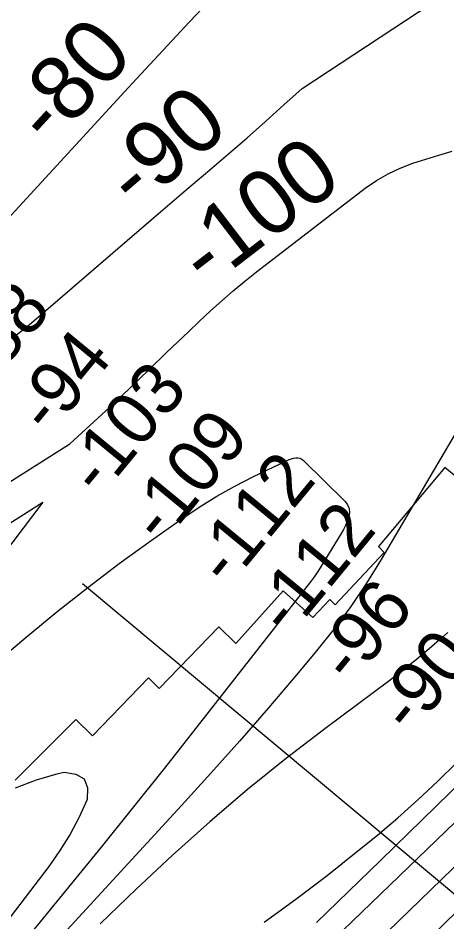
# Model space of a CAD drawing. Extents: x 3598634 to 3636690, y 517270 to 542944.
# Drawn here: x 3604825 to 3605373, y 526222 to 527377 of the extents above; entities that cross this region are included whole.
import ezdxf

# ---------------------------------------------------------------- set-up
doc = ezdxf.new("R2010")
doc.units = 0
for name, color, linetype in [('V-CHAN-NAID', 7, 'Continuous'), ('V-RIVR-RANG', 7, 'Continuous'), ('V-RRAP-RVMT', 7, 'Continuous'), ('V-STRM-FLOW', 7, 'Continuous'), ('V-TOPO-DPTH', 7, 'Continuous'), ('V-TOPO-MAJR', 7, 'Continuous'), ('V-TOPO-MAJR-IDEN', 7, 'Continuous'), ('V-TOPO-MINR', 7, 'Continuous'), ('V-TOPO-MINR-IDEN', 7, 'Continuous')]:
    doc.layers.add(name, color=color, linetype=linetype)

msp = doc.modelspace()

# ---------------------------------------------------------------- linework, layer by layer
at = {"layer": 'V-RIVR-RANG'}
msp.add_line((3605752.3, 525947.2), (3604907, 526654.1), dxfattribs=at)
at = {"layer": 'V-RRAP-RVMT'}
for p, q in [((3605370, 526802.8), (3605285.1, 526701.7)), ((3605523.7, 526673.8), (3605370, 526802.8)), ((3605292.5, 526694), (3605229.9, 526626.9)), ((3605285.1, 526701.7), (3605292.5, 526694)), ((3605163.3, 526645), (3605102.8, 526577.8)), ((3605201.4, 526610.7), (3605163.3, 526645)), ((3605223.1, 526633.9), (3605201.4, 526610.7)), ((3605229.9, 526626.9), (3605223.1, 526633.9)), ((3605081, 526598.9), (3605005, 526520.2)), ((3605102.8, 526577.8), (3605081, 526598.9)), ((3604991.2, 526533.6), (3604919.5, 526459.4)), ((3605005, 526520.2), (3604991.2, 526533.6)), ((3604898.3, 526480.6), (3604820.7, 526403)), ((3604919.5, 526459.4), (3604898.3, 526480.6))]:
    msp.add_line(p, q, dxfattribs=at)
at = {"layer": 'V-STRM-FLOW'}
msp.add_lwpolyline([(3604713.3, 526667.7), (3604856.2, 526758.4), (3604753.9, 526623.5)], dxfattribs=at)
at = {"layer": 'V-TOPO-DPTH'}
msp.add_lwpolyline([(3605155.1, 526007.8), (3605497.3, 526345.9)], dxfattribs=at)
msp.add_lwpolyline([(3605155.1, 526007.8), (3605497.3, 526345.9)], dxfattribs=at)
at = {"layer": 'V-TOPO-MAJR'}
for points in [[(3604098.7, 526331.4), (3604890.7, 526832.8), (3604916.3, 526856.3), (3604941.7, 526879.9), (3604967, 526903.8), (3604992, 526927.9), (3605014.4, 526949.6), (3605028.3, 526963), (3605042.3, 526976.3), (3605056.4, 526989.6), (3605070.5, 527002.9), (3605084.8, 527015.8), (3605099.4, 527028.5), (3605114.3, 527040.8), (3605129.4, 527052.8), (3605268.3, 527159.7), (3605282.5, 527169.5), (3605297.3, 527178.3), (3605312.9, 527185.5), (3605329.1, 527191.6), (3605345.7, 527196.9), (3605362.4, 527202), (3605379.1, 527206.9)], [(3605519.2, 527085.7), (3605500.7, 527048.2), (3605480.6, 527011.4), (3605288.6, 526685.1), (3605269.7, 526654.7), (3605249.8, 526625), (3605228.4, 526596.3), (3605206.1, 526568.3), (3605180.6, 526537.9), (3605144.5, 526495.5), (3605108, 526453.4), (3605071, 526411.8), (3605033.5, 526370.6), (3604541.9, 525836.1), (3604531.7, 525824.9), (3604521.6, 525813.6), (3604511.7, 525802.2), (3604501.9, 525790.7), (3604418.3, 525691.8), (3604367.5, 525630.2), (3604317.7, 525567.9), (3604269.3, 525504.4)], [(3604758.4, 525688), (3605476.3, 526383.5)]]:
    msp.add_lwpolyline(points, dxfattribs=at)
at = {"layer": 'V-TOPO-MINR'}
for points in [[(3606331.2, 528483.3), (3606171, 528346.6), (3606089, 528276.3), (3606007.2, 528205.6), (3605925.9, 528134.5), (3605192.6, 527528.5), (3605117.8, 527450.9), (3605043.8, 527372.4), (3604970.3, 527293.5), (3604747.9, 527052.1)], [(3604818.6, 526969.3), (3604826.3, 526975.3), (3604833.9, 526981.4), (3604841.5, 526987.7), (3604997.7, 527121.7), (3605021.6, 527142.2), (3605045.5, 527162.7), (3605069.5, 527183.2), (3605093.4, 527203.7), (3605117.2, 527224.3), (3605140.8, 527245.1), (3605164.3, 527266.2), (3605187.5, 527287.4), (3605715.9, 527635.2)], [(3604710.8, 526480.7), (3604835, 526585.8), (3604874, 526618), (3604913.5, 526649.4), (3604953.8, 526679.8), (3604994.7, 526709.5), (3605033.6, 526737), (3605055.8, 526751.8), (3605078.4, 526765.9), (3605101.7, 526778.9), (3605125.5, 526791.1), (3605168.4, 526811.8), (3605171.1, 526813), (3605173.8, 526813.9), (3605176.6, 526814.6), (3605179.4, 526815), (3605182.1, 526815), (3605184.7, 526814.5), (3605187.1, 526813.3), (3605189.3, 526811.7), (3605242.5, 526759.4), (3605245.7, 526755), (3605247.7, 526750.2)], [(3605247.7, 526750.2), (3605248.1, 526745.1), (3605247.3, 526739.7), (3605245.3, 526734.1), (3605243, 526728.7), (3605240.3, 526723.4), (3605237.4, 526718.2), (3605208.3, 526670.9), (3605205.9, 526667.2), (3605203.5, 526663.5), (3605200.9, 526660), (3605198.2, 526656.5), (3605011.6, 526418.4), (3604930.9, 526317.2), (3604849, 526216.9), (3604765.5, 526118.1), (3604680.9, 526020.1), (3604540.8, 525860.6), (3604525.5, 525843), (3604510.3, 525825.4), (3604495.2, 525807.6), (3604480.2, 525789.8), (3604361.5, 525647.7), (3604287.8, 525558.3)], [(3605373.6, 526591.7), (3605366.6, 526585.4), (3605350, 526570.9), (3605333.1, 526556.7), (3605315.8, 526543), (3605298.3, 526529.5), (3605218.2, 526469.8), (3605167.6, 526430.9), (3605117.9, 526391), (3605069.5, 526349.5), (3605021.9, 526307.1), (3604975.3, 526263.4), (3604929.4, 526219.1)], [(3605206.1, 526220.9), (3605287.8, 526300.2), (3605429.8, 526439.3)], [(3605139, 526221.2), (3605179.7, 526250.6), (3605219.6, 526281.1), (3605258.9, 526312.5), (3605283.7, 526332.8), (3605309.9, 526354.9), (3605335.5, 526377.6), (3605360.5, 526401), (3605385, 526425)], [(3604821.4, 526393), (3604848, 526403.2), (3604875.6, 526411.3), (3604883.5, 526413.1), (3604898.3, 526410.7), (3604908.9, 526404.7), (3604913.1, 526393.2), (3604913, 526378.2), (3604902.6, 526355.7), (3604891.1, 526333.8), (3604878, 526312.8), (3604863.7, 526292.5), (3604778.2, 526180.7)], [(3604940.3, 525922.3), (3605431.3, 526395.5)], [(3605155.1, 526007.8), (3605497.3, 526345.9)]]:
    msp.add_lwpolyline(points, dxfattribs=at)

# ---------------------------------------------------------------- texts
at = {"layer": 'V-CHAN-NAID'}
msp.add_text('ADM/GROWMARK ', height=100, rotation=316.027, dxfattribs=at).set_placement((3604148.8, 526578.8))
at = {"layer": 'V-RIVR-RANG'}
for s, p in [('-88', (3604786.6, 526904.5)), ('-94', (3604864.8, 526842.2)), ('-103', (3604929.4, 526763.2)), ('-109', (3605008.6, 526702.2)), ('-112', (3605093.2, 526647.6)), ('-112', (3605170.3, 526583.9)), ('-96', (3605250.1, 526523.5)), ('-90', (3605326.7, 526459.2))]:
    msp.add_text(s, height=67, rotation=50.5771, dxfattribs=at).set_placement(p)
at = {"layer": 'V-TOPO-MAJR-IDEN'}
msp.add_text('-100', height=83, rotation=37.5785, dxfattribs=at).set_placement((3605066.1, 527030.3))
at = {"layer": 'V-TOPO-MINR-IDEN'}
for s, rotation, p in [('-80', 47.3443, (3604865.8, 527210.7)), ('-90', 40.5998, (3604975.6, 527130.1))]:
    msp.add_text(s, height=83, rotation=rotation, dxfattribs=at).set_placement(p)

doc.saveas('drawing.dxf')
